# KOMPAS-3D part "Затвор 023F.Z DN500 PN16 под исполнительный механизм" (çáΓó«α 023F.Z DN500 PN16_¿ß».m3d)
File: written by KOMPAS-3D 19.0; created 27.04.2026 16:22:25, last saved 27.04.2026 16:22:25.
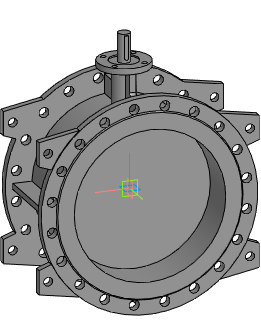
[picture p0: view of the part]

Document properties: Автор: Евгений; Полное имя файла: Z:\3.Личные\kachalov\3d для проектировщиков\1.7 Тип 023F.Z Затвор дисковый поворотный фланцевый с двумя эксцентриками\Затвор 023F.Z DN200-DN1600_исп\_stp_Затвор 023F.Z DN200-DN1600_исп\Затвор 023F.Z DN500 PN16_исп.m3d

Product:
- Part/product: Затвор 023F.Z DN500 PN16 под исполнительный механизм

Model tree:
1. Операция без истории:1  (labels: Затвор 023F.Z DN500 PN16 под исполнительный механизм)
